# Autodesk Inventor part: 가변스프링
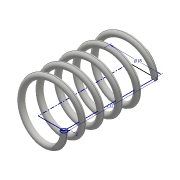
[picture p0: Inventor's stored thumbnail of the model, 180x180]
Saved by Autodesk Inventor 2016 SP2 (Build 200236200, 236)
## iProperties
Created: 2017-12
Part Number: 가변스프링
Material: Generic
Document SubType Name: Modeling
Designer: Administrator
Density: 1 g/cm^3
Appearance: Default
Author: Administrator
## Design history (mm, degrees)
sketch "스케치1"
  geometry: L1 (0, 0)-(9, 0); L2 (9, 0)-(9, 28.5); L3 (9, 28.5)-(0, 28.5); L4 (0, 28.5)-(0, 0); C1 r 1 at (9, 0)
  constraints: 8 end point, 2 parallel, 1 centre point, 1 coincident, 1 horizontal, 1 perpendicular
  dimensions: "d0" = 2 diameter of C1; "d1" = 28.5 distance of L1.end L2.end (derived); "d2" = 18 diameter of L2 L4
feature "코일1" pitch "d3" = 10; turns "d5" = 5; dims "d4" = 28.5 (= d1), "d6" = 0, angle "d7" = 90 deg, angle "d8" = 90 deg, "d9" = 0, "d10" = 0
sketch "스케치2"
  geometry: L1 (-10, 0)-(-8, 0) reference; 1 further point
  constraints: 1 horizontal alignment
extrude "돌출1" cut sketch "스케치2" stored distance "d11" = 10; taper "d12" = 0 deg
node "작업 평면1"
sketch "스케치3"
  geometry: L1 (1, 0)-(-1, 0) reference; 1 further point
  constraints: 1 horizontal alignment
extrude "돌출2" cut sketch "스케치3" stored distance "d14" = 10; taper "d15" = 0 deg
node "솔리드1"
node "절단 모서리 투영1"
node "절단 모서리 투영2"
other parameters: "d13" = 90 deg
